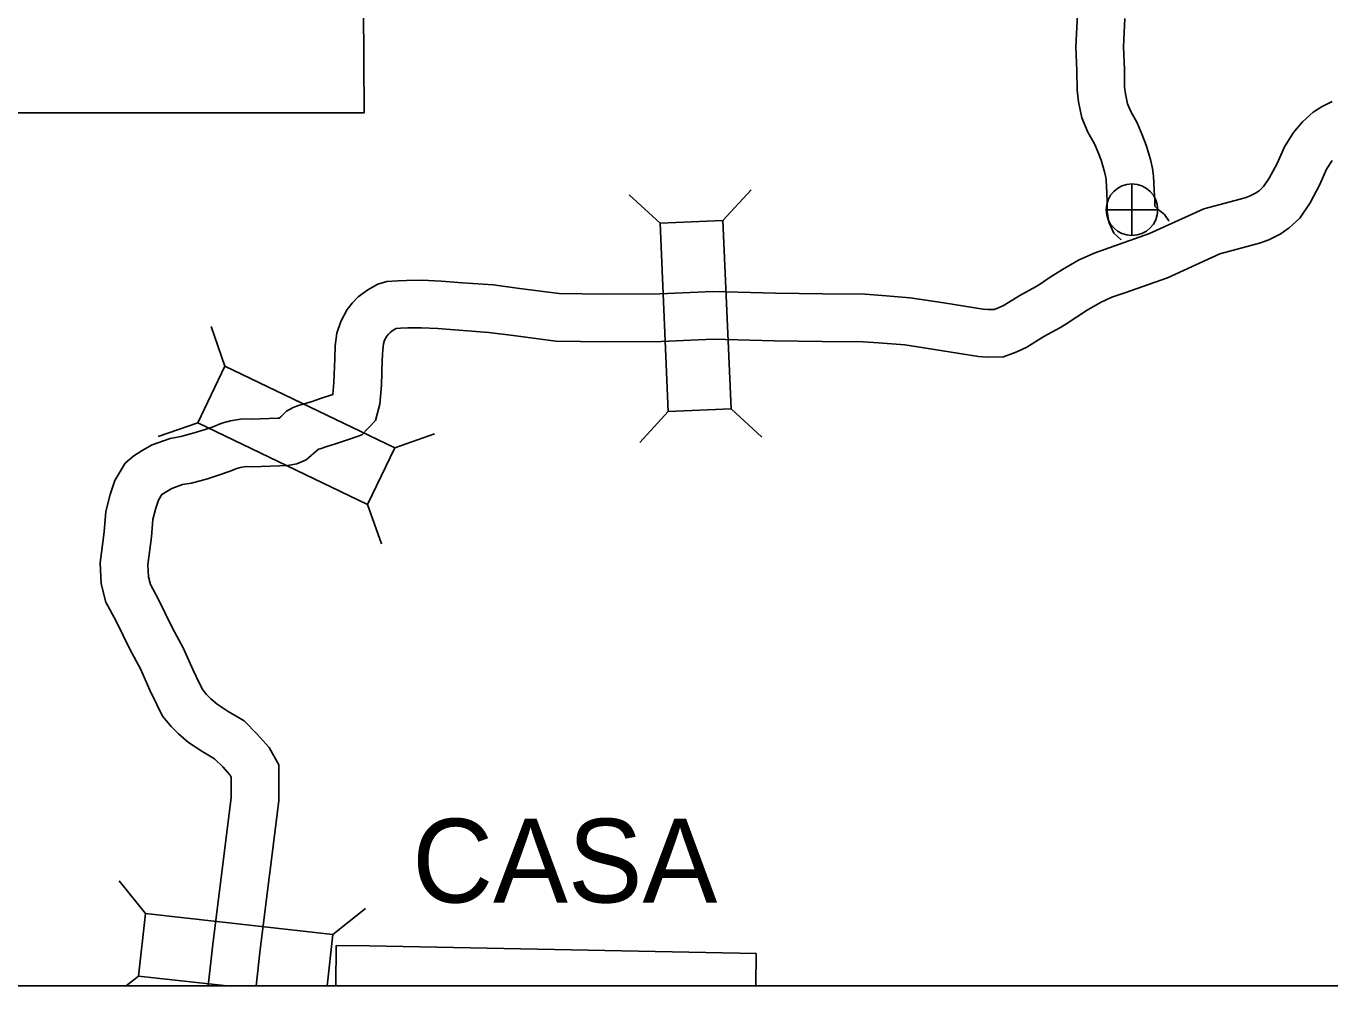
# Model space of a CAD drawing. Extents: x 1374139 to 1377472, y 1168351 to 1170484.
# Drawn here: x 1374645 to 1374727.2, y 1169604.3 to 1169664.8 of the extents above; entities that cross this region are included whole.
import ezdxf

# ---------------------------------------------------------------- set-up
doc = ezdxf.new("R2010")
doc.units = 0
doc.layers.add('26', color=7, linetype='Continuous')
doc.layers.add('Default', color=7, linetype='Continuous')

msp = doc.modelspace()

# ---------------------------------------------------------------- linework, layer by layer
at = {"layer": '26'}
msp.add_lwpolyline([(1374299.152, 1170388.771), (1375028.549, 1170388.771), (1375028.549, 1169604.285), (1374299.152, 1169604.285)], close=True, dxfattribs=at)
at = {"layer": 'Default'}
for p, q in [((1374714.716, 1169651.59), (1374714.716, 1169654.84)), ((1374684.987, 1169652.361), (1374683.042, 1169654.146)), ((1374688.943, 1169652.53), (1374690.728, 1169654.475)), ((1374713.092, 1169653.215), (1374716.341, 1169653.215)), ((1374657.56, 1169643.361), (1374656.687, 1169645.852)), ((1374689.452, 1169640.661), (1374691.397, 1169638.876)), ((1374685.495, 1169640.492), (1374683.71, 1169638.547)), ((1374655.844, 1169639.792), (1374653.352, 1169638.919)), ((1374668.266, 1169638.212), (1374670.758, 1169639.085)), ((1374666.55, 1169634.643), (1374667.423, 1169632.152)), ((1374652.55, 1169608.844), (1374650.901, 1169610.906)), ((1374652.55, 1169608.844), (1374652.11, 1169604.908)), ((1374664.356, 1169607.525), (1374652.55, 1169608.844)), ((1374664.356, 1169607.525), (1374666.418, 1169609.173)), ((1374663.994, 1169604.285), (1374664.356, 1169607.525)), ((1374664.571, 1169606.842), (1374664.543, 1169604.285)), ((1374666.673, 1169606.803), (1374664.571, 1169606.842)), ((1374691.038, 1169606.331), (1374666.673, 1169606.803)), ((1374691.022, 1169604.285), (1374691.038, 1169606.331)), ((1374652.11, 1169604.908), (1374651.33, 1169604.285)), ((1374652.11, 1169604.908), (1374657.692, 1169604.285)), ((1374657.692, 1169604.285), (1374663.994, 1169604.285)), ((1374664.543, 1169604.285), (1374691.022, 1169604.285))]:
    msp.add_line(p, q, dxfattribs=at)
for points in [[(1374700.109, 1169686.03), (1374692.682, 1169686.381), (1374666.167, 1169685.836), (1374666.331, 1169659.315), (1374639.748, 1169659.329), (1374639.928, 1169632.938), (1374613.437, 1169632.866), (1374613.711, 1169606.658), (1374612.681, 1169606.654), (1374587.094, 1169606.782), (1374586.375, 1169606.748), (1374586.378, 1169604.285)], [(1374711.278, 1169665.518), (1374711.176, 1169663.488), (1374711.247, 1169661.973), (1374711.256, 1169660.758), (1374711.344, 1169660.015), (1374711.564, 1169659.001), (1374711.934, 1169658.098), (1374712.35, 1169657.366), (1374712.58, 1169656.816), (1374712.768, 1169656.33), (1374712.979, 1169655.608), (1374713.066, 1169655.255), (1374713.088, 1169655.083), (1374713.124, 1169654.288), (1374713.162, 1169653.695), (1374713.16, 1169653.105), (1374713.258, 1169652.429), (1374713.564, 1169651.745), (1374714.007, 1169651.329), (1374714.009, 1169651.328)], [(1374714.269, 1169665.267), (1374714.179, 1169663.482), (1374714.246, 1169662.055), (1374714.255, 1169660.946), (1374714.306, 1169660.511), (1374714.44, 1169659.894), (1374714.637, 1169659.413), (1374715.049, 1169658.69), (1374715.363, 1169657.935), (1374715.612, 1169657.294), (1374715.876, 1169656.388), (1374716.02, 1169655.807), (1374716.079, 1169655.34), (1374716.119, 1169654.454), (1374716.163, 1169653.786), (1374716.161, 1169653.437), (1374716.22, 1169653.387), (1374716.446, 1169653.175), (1374716.761, 1169652.91), (1374717.042, 1169652.523), (1374717.058, 1169652.505)], [(1374727.338, 1169660.033), (1374726.705, 1169659.722), (1374726.132, 1169659.36), (1374725.453, 1169658.758), (1374724.889, 1169658.084), (1374724.325, 1169657.171), (1374723.856, 1169656.125), (1374723.371, 1169655.199), (1374723.015, 1169654.672), (1374722.725, 1169654.411), (1374722.505, 1169654.251), (1374722.162, 1169654.084), (1374721.84, 1169653.967), (1374719.237, 1169653.264), (1374715.824, 1169651.713), (1374713.286, 1169650.809), (1374712.333, 1169650.487), (1374711.354, 1169650.037), (1374710.33, 1169649.452), (1374709.556, 1169648.955), (1374708.943, 1169648.538), (1374708.676, 1169648.381), (1374707.652, 1169647.808), (1374706.667, 1169647.199), (1374706.306, 1169647.028), (1374706.042, 1169646.933), (1374705.643, 1169646.92), (1374705.317, 1169646.942)], [(1374727.328, 1169656.324), (1374726.981, 1169655.763), (1374726.556, 1169654.814), (1374725.951, 1169653.659), (1374725.296, 1169652.689), (1374724.615, 1169652.076), (1374724.054, 1169651.668), (1374723.334, 1169651.318), (1374722.747, 1169651.104), (1374720.255, 1169650.432), (1374716.95, 1169648.93), (1374714.269, 1169647.975), (1374713.442, 1169647.695), (1374712.727, 1169647.366), (1374711.886, 1169646.886), (1374711.211, 1169646.452), (1374710.552, 1169646.004), (1374710.172, 1169645.78), (1374709.173, 1169645.222), (1374708.101, 1169644.559), (1374707.457, 1169644.254), (1374706.614, 1169643.951), (1374705.595, 1169643.917), (1374705.047, 1169643.953)], [(1374705.46, 1169646.925), (1374702.857, 1169647.35), (1374700.748, 1169647.671), (1374698.976, 1169647.818), (1374697.894, 1169647.898), (1374695.228, 1169647.91), (1374692.244, 1169647.949), (1374688.308, 1169648.059), (1374684.965, 1169647.916), (1374681.528, 1169647.889), (1374678.621, 1169647.926), (1374676.116, 1169648.258), (1374674.483, 1169648.471), (1374672.521, 1169648.609), (1374671.186, 1169648.715), (1374669.987, 1169648.782), (1374669.001, 1169648.759), (1374668.453, 1169648.741), (1374667.766, 1169648.69), (1374667.197, 1169648.515), (1374666.561, 1169648.162), (1374665.947, 1169647.721), (1374665.585, 1169647.317), (1374665.264, 1169646.925), (1374664.855, 1169646.178), (1374664.616, 1169645.44), (1374664.508, 1169644.639), (1374664.48, 1169643.834), (1374664.423, 1169642.318), (1374664.368, 1169641.573), (1374663.524, 1169641.287), (1374663.062, 1169641.135), (1374662.71, 1169641.022), (1374662.407, 1169640.938), (1374662.133, 1169640.844), (1374661.855, 1169640.747), (1374661.433, 1169640.517), (1374661.091, 1169640.167), (1374660.986, 1169640.071), (1374660.902, 1169640.068), (1374659.241, 1169640.012), (1374658.675, 1169640.029), (1374657.916, 1169639.906), (1374657.358, 1169639.76), (1374656.749, 1169639.515), (1374656.321, 1169639.359), (1374655.63, 1169639.142), (1374654.791, 1169638.915), (1374654.107, 1169638.793), (1374652.967, 1169638.387), (1374652.353, 1169638.04), (1374651.814, 1169637.7), (1374651.265, 1169637.237), (1374650.626, 1169636.149), (1374650.337, 1169635.259), (1374650.052, 1169634.202), (1374649.943, 1169632.91), (1374649.703, 1169630.953), (1374649.76, 1169629.636), (1374650.051, 1169628.477), (1374650.711, 1169627.269), (1374651.581, 1169625.474), (1374652.24, 1169624.266), (1374652.831, 1169622.937), (1374653.274, 1169622.021), (1374653.634, 1169621.296), (1374654.182, 1169620.635), (1374654.638, 1169620.171), (1374655.271, 1169619.638), (1374656.161, 1169619.045), (1374656.912, 1169618.599), (1374657.423, 1169618.09), (1374657.895, 1169617.566), (1374657.963, 1169617.444), (1374657.963, 1169616.144), (1374656.803, 1169606.927), (1374656.508, 1169604.285)], [(1374705.047, 1169643.953), (1374702.39, 1169644.387), (1374700.398, 1169644.689), (1374698.741, 1169644.827), (1374697.777, 1169644.898), (1374695.202, 1169644.91), (1374692.182, 1169644.949), (1374688.33, 1169645.057), (1374685.041, 1169644.916), (1374681.52, 1169644.889), (1374678.404, 1169644.929), (1374675.725, 1169645.283), (1374674.184, 1169645.485), (1374672.296, 1169645.617), (1374670.984, 1169645.722), (1374669.938, 1169645.78), (1374669.086, 1169645.761), (1374668.615, 1169645.745), (1374668.352, 1169645.725), (1374668.17, 1169645.624), (1374667.963, 1169645.475), (1374667.863, 1169645.363), (1374667.761, 1169645.24), (1374667.623, 1169644.986), (1374667.553, 1169644.772), (1374667.501, 1169644.385), (1374667.478, 1169643.725), (1374667.419, 1169642.15), (1374667.33, 1169640.955), (1374667.05, 1169639.921), (1374666.198, 1169639.034), (1374665.537, 1169638.802), (1374664.475, 1169638.442), (1374663.987, 1169638.281), (1374663.568, 1169638.147), (1374663.454, 1169638.115), (1374662.68, 1169637.451), (1374662.096, 1169637.188), (1374661.529, 1169637.087), (1374661.003, 1169637.07), (1374659.247, 1169637.01), (1374658.872, 1169637.022), (1374658.537, 1169636.967), (1374658.302, 1169636.906), (1374657.825, 1169636.714), (1374657.285, 1169636.517), (1374656.471, 1169636.262), (1374655.447, 1169635.985), (1374654.879, 1169635.884), (1374654.219, 1169635.648), (1374653.891, 1169635.462), (1374653.591, 1169635.274), (1374653.379, 1169634.913), (1374653.214, 1169634.404), (1374653.019, 1169633.681), (1374652.927, 1169632.601), (1374652.711, 1169630.834), (1374652.744, 1169630.071), (1374652.867, 1169629.58), (1374653.379, 1169628.643), (1374654.249, 1169626.848), (1374654.932, 1169625.596), (1374655.552, 1169624.2), (1374655.968, 1169623.341), (1374656.166, 1169622.942), (1374656.41, 1169622.648), (1374656.679, 1169622.375), (1374657.075, 1169622.041), (1374657.76, 1169621.585), (1374658.764, 1169620.988), (1374659.597, 1169620.159), (1374660.351, 1169619.322), (1374660.963, 1169618.224), (1374660.963, 1169615.956), (1374659.782, 1169606.574), (1374659.527, 1169604.285)]]:
    msp.add_lwpolyline(points, dxfattribs=at)
for points in [[(1374684.987, 1169652.361), (1374685.495, 1169640.492), (1374689.452, 1169640.661), (1374688.943, 1169652.53)], [(1374655.844, 1169639.792), (1374666.55, 1169634.643), (1374668.266, 1169638.212), (1374657.56, 1169643.361)]]:
    msp.add_lwpolyline(points, close=True, dxfattribs=at)
msp.add_circle((1374714.716, 1169653.215), 1.625, dxfattribs=at)

# ---------------------------------------------------------------- texts
msp.add_text('CASA', height=5.28, dxfattribs=at).set_placement((1374669.362, 1169609.543))

doc.saveas('drawing.dxf')
